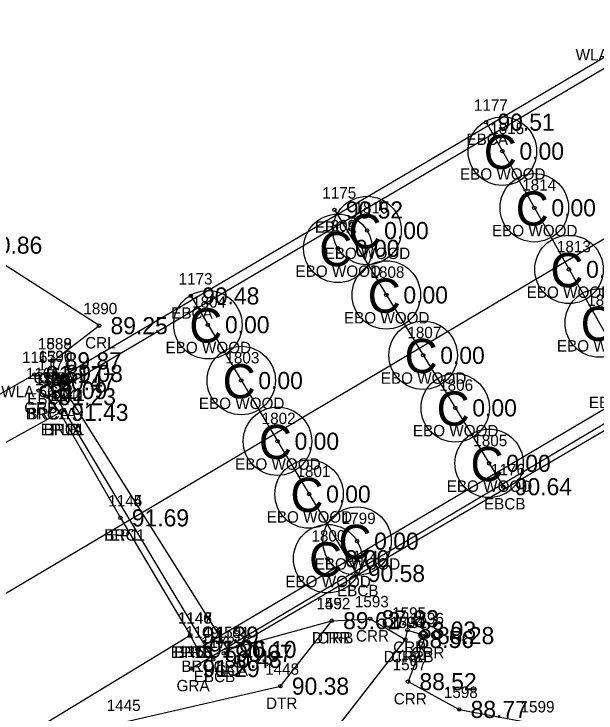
# Model space of a CAD drawing. Extents: x 2529517 to 2532038, y 935000 to 936944.
# Drawn here: x 2531075.4 to 2531126.5, y 935921.4 to 935982.7 of the extents above; entities that cross this region are included whole.
import ezdxf

# ---------------------------------------------------------------- set-up
doc = ezdxf.new("R2010")
doc.units = 0
for name, color, linetype in [('Default', 7, 'Continuous'), ('RD_EX_Bridge', 7, 'Continuous'), ('RD_EX_Bridge_txCode', 7, 'Continuous'), ('RD_EX_GuardRail', 7, 'Continuous'), ('RD_EX_GuardRail_txCode', 7, 'Continuous'), ('RD_EX_H2O', 7, 'Continuous'), ('RD_EX_H2O_txCode', 7, 'Continuous'), ('RD_EX_Road', 7, 'Continuous'), ('RD_EX_Road_txCode', 7, 'Continuous'), ('RD_EX_TX_Bridge_ELEV', 7, 'Continuous'), ('RD_EX_TX_GuardRail_ELEV', 7, 'Continuous'), ('RD_EX_TX_H2O_ELEV', 7, 'Continuous'), ('RD_EX_TX_Road_ELEV', 7, 'Continuous'), ('RD_EX_TX_UT_ELEV', 7, 'Continuous'), ('RD_EX_UT', 7, 'Continuous'), ('RD_EX_UT_txCode', 7, 'Continuous'), ('RD_HC_Cl', 7, 'Continuous'), ('RD_SMD_Locator', 7, 'Continuous')]:
    doc.layers.add(name, color=color, linetype=linetype)

msp = doc.modelspace()

# ---------------------------------------------------------------- linework, layer by layer
at = {"layer": 'Default'}
msp.add_line((2530557.048, 935625.341), (2531768.068, 936342.554), dxfattribs=at)
at = {"layer": 'RD_EX_Bridge'}
for p, q in [((2531078.356, 935949.14), (2531168.645, 936002.424)), ((2531116.822, 935973.21), (2531130.734, 935948.542)), ((2531103.53, 935965.513), (2531118.344, 935941.245)), ((2531090.929, 935957.972), (2531105.458, 935933.64)), ((2531078.311, 935950.44), (2531092.894, 935926.105))]:
    msp.add_line(p, q, dxfattribs=at)
msp.add_lwpolyline([(2531078.356, 935949.14), (2531079.452, 935947.762), (2531084.764, 935938.512), (2531090.884, 935928.231), (2531091.526, 935926.997), (2531181.787, 935980.32), (2531180.823, 935981.996), (2531175.162, 935992.092), (2531169.648, 936000.767), (2531168.645, 936002.424)], dxfattribs=at)
for centre in [(2531118.257, 935970.666), (2531121.057, 935965.701), (2531106.391, 935963.706), (2531103.83, 935962.143), (2531124.103, 935960.301), (2531108.08, 935958.059), (2531092.436, 935955.448), (2531126.755, 935955.597), (2531111.31, 935952.767), (2531095.358, 935950.554), (2531114.124, 935948.158), (2531098.537, 935945.231), (2531117.094, 935943.293), (2531101.305, 935940.594), (2531105.515, 935936.469), (2531102.94, 935934.931)]:
    msp.add_circle(centre, 3, dxfattribs=at)
at = {"layer": 'RD_EX_GuardRail'}
for p, q in [((2531168.701, 936003.319), (2531077.589, 935949.675)), ((2531090.959, 935925.298), (2531182.654, 935979.665))]:
    msp.add_line(p, q, dxfattribs=at)
at = {"layer": 'RD_EX_H2O'}
for points in [[(2531078.875, 935952.281), (2531078.875, 935952.281), (2531082.899, 935955.367), (2531071.893, 935962.427), (2531052.521, 935981.817), (2531042.661, 936018.537), (2531050.401, 936038.586), (2531079.351, 936050.478), (2531076.459, 936052.289), (2531062.769, 936059.407), (2531060.273, 936060.115), (2531061.981, 936077.759), (2531053.988, 936081.477), (2531023.23, 936060.573), (2531009.04, 936063.638), (2530981.915, 936072.848), (2530952.276, 936069.689), (2530922.526, 936086.42), (2530896.36, 936118.007), (2530886.535, 936120.086), (2530870.436, 936126.503), (2530844.881, 936119.109), (2530827.398, 936131.929), (2530794.882, 936161.74)], [(2531078.875, 935952.281), (2531078.96, 935951.177), (2531094.183, 935926.972), (2531103.295, 935929.494), (2531106.667, 935929.665), (2531109.751, 935927.847), (2531109.937, 935928.671), (2531111.529, 935928.19), (2531109.984, 935924.149), (2531114.473, 935921.713), (2531121.2, 935920.45), (2531134.651, 935891.599), (2531155.43, 935754.455), (2531173.735, 935652.906), (2531186.187, 935572.514), (2531201.43, 935446.699)], [(2531014.512, 935871.147), (2531011.198, 935876.261), (2531054.239, 935902.022), (2531084.907, 935920.574), (2531098.798, 935923.754), (2531103.295, 935929.494)], [(2531014.512, 935871.147), (2531057.214, 935896.364), (2531090.236, 935914.424), (2531102.959, 935919.079), (2531109.751, 935927.847)]]:
    msp.add_lwpolyline(points, dxfattribs=at)
at = {"layer": 'RD_EX_Road'}
for points in [[(2530213.129, 935600.159), (2530313.796, 935600.808), (2530414.146, 935601.135), (2530426.724, 935601.431), (2530429.462, 935603.551), (2530467.667, 935608.622), (2530486.463, 935612.382), (2530518.022, 935622.553), (2530522.163, 935623.679), (2530567.909, 935646.012), (2530609.299, 935670.154), (2530695.461, 935720.024), (2530775.853, 935769.269), (2530868.285, 935824.026), (2530924.837, 935856.951), (2530956.207, 935875.821), (2531040.717, 935926.378), (2531079.452, 935947.762)], [(2531079.452, 935947.762), (2531084.764, 935938.512), (2531090.884, 935928.231)], [(2530212.444, 935579.718), (2530312.608, 935580.142), (2530402.982, 935580.636), (2530451.057, 935579.535), (2530466.913, 935580.348), (2530487.453, 935583.291), (2530533.43, 935598.455), (2530580.282, 935625.084), (2530621.694, 935649.225), (2530704.615, 935698.354), (2530718.668, 935706.376), (2530795.45, 935752.358), (2530871.328, 935796.67), (2530882.405, 935803.04), (2530947.168, 935842.26), (2530966.001, 935852.419), (2530992.723, 935868.002), (2531009.487, 935879.014), (2531052.394, 935904.854), (2531090.884, 935928.231)]]:
    msp.add_lwpolyline(points, dxfattribs=at)
at = {"layer": 'RD_EX_UT'}
for p, q in [((2531093.836, 935926.635), (2531177.851, 935975.895)), ((2531077.223, 935951.092), (2531066.609, 935945.067))]:
    msp.add_line(p, q, dxfattribs=at)
at = {"layer": 'RD_HC_Cl'}
msp.add_line((2530557.048, 935625.341), (2531768.068, 936342.554), dxfattribs=at)
at = {"layer": 'RD_SMD_Locator'}
for centre in [(2531116.822, 935973.21), (2531118.257, 935970.666), (2531103.53, 935965.513), (2531121.057, 935965.701), (2531106.391, 935963.706), (2531103.83, 935962.143), (2531124.103, 935960.301), (2531108.08, 935958.059), (2531090.929, 935957.972), (2531082.899, 935955.367), (2531092.436, 935955.448), (2531111.311, 935952.767), (2531078.875, 935952.281), (2531078.875, 935952.281), (2531078.875, 935952.281), (2531077.223, 935951.092), (2531078.96, 935951.177), (2531078.311, 935950.44), (2531095.358, 935950.554), (2531077.589, 935949.675), (2531078.356, 935949.14), (2531078.356, 935949.14), (2531079.452, 935947.762), (2531079.452, 935947.762), (2531079.452, 935947.762), (2531114.124, 935948.158), (2531098.537, 935945.231), (2531117.094, 935943.293), (2531118.344, 935941.245), (2531101.305, 935940.594), (2531084.764, 935938.512), (2531084.764, 935938.512), (2531105.516, 935936.469), (2531102.94, 935934.931), (2531105.458, 935933.64), (2531103.295, 935929.494), (2531103.295, 935929.494), (2531106.667, 935929.665), (2531109.937, 935928.671), (2531090.884, 935928.231), (2531090.884, 935928.231), (2531090.884, 935928.231), (2531111.529, 935928.19), (2531109.751, 935927.847), (2531109.751, 935927.847), (2531091.526, 935926.997), (2531094.183, 935926.972), (2531092.894, 935926.105), (2531093.836, 935926.635), (2531090.959, 935925.298), (2531098.798, 935923.754), (2531109.984, 935924.149), (2531114.473, 935921.713)]:
    msp.add_circle(centre, 0.15, dxfattribs=at)

# ---------------------------------------------------------------- texts
at = {"layer": 'RD_EX_Bridge'}
for p in [(2531116.626, 935969.104), (2531119.426, 935964.14), (2531104.76, 935962.145), (2531102.199, 935960.582), (2531122.472, 935958.739), (2531106.449, 935956.498), (2531090.805, 935953.886), (2531125.125, 935954.036), (2531109.68, 935951.206), (2531093.728, 935948.992), (2531112.493, 935946.597), (2531096.906, 935943.669), (2531115.463, 935941.732), (2531099.675, 935939.033), (2531103.885, 935934.908), (2531101.309, 935933.37)]:
    msp.add_text('C', height=3, dxfattribs=at).set_placement(p)
at = {"layer": 'RD_EX_Bridge_txCode'}
for s, p in [('1177', (2531115.759, 935974.21)), ('1815', (2531117.194, 935972.166)), ('EBCA', (2531115.106, 935971.21)), ('EBO WOOD', (2531114.54, 935968.166)), ('1814', (2531119.994, 935967.201)), ('1175', (2531102.467, 935966.513)), ('1810', (2531105.288, 935965.206)), ('EBCA', (2531101.814, 935963.513)), ('1809', (2531102.444, 935963.643)), ('EBO WOOD', (2531117.341, 935963.201)), ('1813', (2531123.04, 935961.801)), ('EBO WOOD', (2531102.674, 935961.206)), ('EBO WOOD', (2531100.114, 935959.643)), ('1173', (2531089.866, 935958.972)), ('1808', (2531106.694, 935959.559)), ('EBO WOOD', (2531120.386, 935957.801)), ('1804', (2531091.05, 935956.948)), ('1812', (2531125.693, 935957.097)), ('EBCA', (2531089.213, 935955.972)), ('EBO WOOD', (2531104.364, 935955.559)), ('1807', (2531109.925, 935954.267)), ('EBO WOOD', (2531088.72, 935952.948)), ('EBO WOOD', (2531123.039, 935953.097)), ('1803', (2531093.973, 935952.054)), ('1171', (2531077.531, 935951.44)), ('1140', (2531077.253, 935950.14)), ('1139', (2531077.293, 935950.14)), ('EBO WOOD', (2531107.594, 935950.267)), ('1806', (2531112.715, 935949.658)), ('1141', (2531078.672, 935948.762)), ('EBCA', (2531076.594, 935948.44)), ('EBO WOOD', (2531091.642, 935948.054)), ('EBO WOOD', (2531125.839, 935948.132)), ('BRC1A', (2531076.45, 935947.14)), ('BRCA', (2531076.615, 935947.14)), ('1802', (2531097.151, 935946.731)), ('BRC1', (2531078.034, 935945.762)), ('EBO WOOD', (2531110.407, 935945.658)), ('1805', (2531115.708, 935944.793)), ('EBO WOOD', (2531094.82, 935942.731)), ('1801', (2531100.203, 935942.094)), ('1176', (2531117.258, 935942.245)), ('EBO WOOD', (2531113.377, 935940.793)), ('1144', (2531083.701, 935939.512)), ('EBCB', (2531116.644, 935939.245)), ('EBO WOOD', (2531097.589, 935938.094)), ('1799', (2531104.169, 935937.969)), ('BRC1', (2531083.347, 935936.512)), ('1800', (2531101.515, 935936.431)), ('1174', (2531104.395, 935934.64)), ('EBO WOOD', (2531101.799, 935933.969)), ('EBO WOOD', (2531099.223, 935932.431)), ('EBCB', (2531103.757, 935931.64)), ('1146', (2531089.797, 935929.231)), ('1149', (2531090.463, 935927.997)), ('1172', (2531091.831, 935927.105)), ('BRC1', (2531089.467, 935926.231)), ('BRC1', (2531090.108, 935924.997)), ('EBCB', (2531091.193, 935924.105))]:
    msp.add_text(s, height=1, dxfattribs=at).set_placement(p)
at = {"layer": 'RD_EX_GuardRail_txCode'}
for s, p in [('1166', (2531076.479, 935950.675)), ('GRB', (2531076.337, 935947.675)), ('1150', (2531089.856, 935926.298)), ('GRA', (2531089.691, 935923.298))]:
    msp.add_text(s, height=1, dxfattribs=at).set_placement(p)
at = {"layer": 'RD_EX_H2O_txCode'}
for s, p in [('1890', (2531081.513, 935956.367)), ('1589', (2531077.529, 935953.281)), ('1888', (2531077.529, 935953.281)), ('1889', (2531077.529, 935953.281)), ('CRL', (2531081.671, 935953.367)), ('1590', (2531077.574, 935952.177)), ('CRRA', (2531077.135, 935950.281)), ('CRLA', (2531077.159, 935950.281)), ('CRL', (2531077.647, 935950.281)), ('CRR', (2531077.708, 935949.177)), ('1452', (2531101.948, 935930.494)), ('1592', (2531101.948, 935930.494)), ('1593', (2531105.321, 935930.665)), ('1595', (2531108.591, 935929.671)), ('1596', (2531110.159, 935929.19)), ('1594', (2531108.404, 935928.847)), ('1451', (2531108.688, 935928.847)), ('1591', (2531093.12, 935927.972)), ('DTRB', (2531101.554, 935927.494)), ('CRR', (2531102.043, 935927.494)), ('CRR', (2531105.415, 935927.665)), ('CRR', (2531108.685, 935926.671)), ('CRR', (2531110.277, 935926.19)), ('DTR1B', (2531107.845, 935925.847)), ('CRR', (2531108.499, 935925.847)), ('CRR', (2531092.931, 935924.972)), ('1448', (2531097.452, 935924.754)), ('1597', (2531108.637, 935925.149)), ('1598', (2531113.126, 935922.713)), ('DTR', (2531097.531, 935921.754)), ('CRR', (2531108.732, 935922.149)), ('1445', (2531083.561, 935921.574)), ('1599', (2531119.854, 935921.45))]:
    msp.add_text(s, height=1, dxfattribs=at).set_placement(p)
at = {"layer": 'RD_EX_Road_txCode'}
for s, p in [('1142', (2531078.389, 935948.762)), ('1143', (2531078.389, 935948.762)), ('EPLB', (2531077.775, 935945.762)), ('EP1A', (2531078.042, 935945.762)), ('1145', (2531083.701, 935939.512)), ('EP1', (2531083.843, 935936.512)), ('1148', (2531089.821, 935929.231)), ('1147', (2531089.821, 935929.231)), ('EPRB', (2531089.183, 935926.231)), ('EP1B', (2531089.49, 935926.231))]:
    msp.add_text(s, height=1, dxfattribs=at).set_placement(p)
at = {"layer": 'RD_EX_TX_Bridge_ELEV'}
for s, p in [('90.51', (2531117.822, 935972.46)), ('0.00', (2531119.757, 935969.916)), ('90.52', (2531104.53, 935964.763)), ('0.00', (2531122.557, 935964.951)), ('0.00', (2531107.891, 935962.956)), ('0.00', (2531105.33, 935961.393)), ('0.00', (2531125.603, 935959.551)), ('90.48', (2531091.929, 935957.222)), ('0.00', (2531109.58, 935957.309)), ('0.00', (2531093.936, 935954.698)), ('0.00', (2531112.811, 935952.017)), ('90.47', (2531079.311, 935949.69)), ('0.00', (2531096.858, 935949.804)), ('91.23', (2531079.356, 935948.39)), ('91.23', (2531079.356, 935948.39)), ('91.43', (2531080.452, 935947.012)), ('0.00', (2531115.624, 935947.408)), ('0.00', (2531100.037, 935944.481)), ('0.00', (2531118.594, 935942.543)), ('90.64', (2531119.344, 935940.495)), ('0.00', (2531102.805, 935939.844)), ('91.69', (2531085.764, 935937.762)), ('0.00', (2531107.016, 935935.719)), ('0.00', (2531104.44, 935934.181)), ('90.58', (2531106.458, 935932.89)), ('91.39', (2531091.884, 935927.481)), ('91.26', (2531092.526, 935926.247)), ('90.48', (2531093.894, 935925.355))]:
    msp.add_text(s, height=1.5, dxfattribs=at).set_placement(p)
at = {"layer": 'RD_EX_TX_GuardRail_ELEV'}
for s, p in [('91.09', (2531078.589, 935948.925)), ('91.29', (2531091.959, 935924.548))]:
    msp.add_text(s, height=1.5, dxfattribs=at).set_placement(p)
at = {"layer": 'RD_EX_TX_H2O_ELEV'}
for s, p in [('90.86', (2531072.893, 935961.677)), ('89.25', (2531083.899, 935954.617)), ('89.87', (2531079.875, 935951.531)), ('89.87', (2531079.875, 935951.531)), ('89.87', (2531079.875, 935951.531)), ('89.08', (2531079.96, 935950.427)), ('89.62', (2531104.295, 935928.744)), ('89.62', (2531104.295, 935928.744)), ('87.83', (2531107.667, 935928.915)), ('88.03', (2531110.937, 935927.921)), ('88.28', (2531112.529, 935927.44)), ('88.56', (2531110.751, 935927.097)), ('88.56', (2531110.751, 935927.097)), ('90.10', (2531095.183, 935926.222)), ('90.38', (2531099.798, 935923.004)), ('88.52', (2531110.984, 935923.399)), ('88.77', (2531115.473, 935920.963))]:
    msp.add_text(s, height=1.5, dxfattribs=at).set_placement(p)
at = {"layer": 'RD_EX_TX_Road_ELEV'}
for s, p in [('91.43', (2531080.452, 935947.012)), ('91.43', (2531080.452, 935947.012)), ('91.69', (2531085.764, 935937.762)), ('91.39', (2531091.884, 935927.481)), ('91.39', (2531091.884, 935927.481))]:
    msp.add_text(s, height=1.5, dxfattribs=at).set_placement(p)
at = {"layer": 'RD_EX_TX_UT_ELEV'}
for s, p in [('91.17', (2531078.223, 935950.342)), ('90.67', (2531094.836, 935925.885))]:
    msp.add_text(s, height=1.5, dxfattribs=at).set_placement(p)
at = {"layer": 'RD_EX_UT_txCode'}
for s, p in [('WLA 6CI', (2531124.682, 935978.619)), ('1167', (2531076.136, 935952.092)), ('WLA 6CI', (2531074.317, 935949.092)), ('1151', (2531093.056, 935927.635)), ('UGCA', (2531092.088, 935924.635))]:
    msp.add_text(s, height=1, dxfattribs=at).set_placement(p)

doc.saveas('drawing.dxf')
